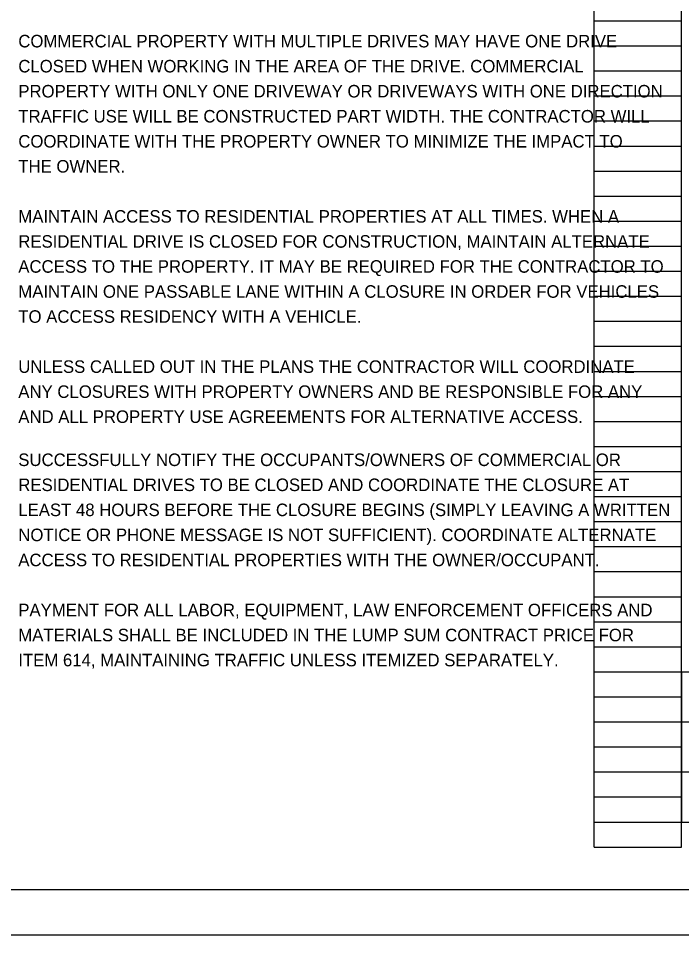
# Model space of a CAD drawing. Extents: x -1.3 to 43.7, y -2.4 to 22.
# Drawn here: x 17.24 to 24.66, y 0 to 10.25 of the extents above; entities that cross this region are included whole.
import ezdxf

# ---------------------------------------------------------------- set-up
doc = ezdxf.new("R2010")
doc.units = 0
for name, color, linetype in [('SH_Border', 7, 'Continuous'), ('SH_Cut_Line', 7, 'Continuous'), ('SH_Data', 7, 'Continuous'), ('SH_Text', 7, 'Continuous')]:
    doc.layers.add(name, color=color, linetype=linetype)

msp = doc.modelspace()

# ---------------------------------------------------------------- linework, layer by layer
at = {"layer": 'SH_Border'}
msp.add_lwpolyline([(1.5, 21.5), (33.5, 21.5), (33.5, 0.5), (1.5, 0.5)], close=True, dxfattribs=at)
at = {"layer": 'SH_Cut_Line'}
msp.add_lwpolyline([(0, 0), (34, 0), (34, 22), (0, 22)], close=True, dxfattribs=at)
at = {"layer": 'SH_Data'}
for p, q in [((23.68, 0.98), (23.68, 21.14)), ((24.66, 0.98), (24.66, 21.14)), ((23.68, 10.22), (24.66, 10.22)), ((23.68, 9.94), (24.66, 9.94)), ((23.68, 9.66), (24.66, 9.66)), ((23.68, 9.38), (24.66, 9.38)), ((23.68, 9.1), (24.66, 9.1)), ((23.68, 8.82), (24.66, 8.82)), ((23.68, 8.54), (24.66, 8.54)), ((23.68, 8.26), (24.66, 8.26)), ((23.68, 7.98), (24.66, 7.98)), ((23.68, 7.7), (24.66, 7.7)), ((23.68, 7.42), (24.66, 7.42)), ((23.68, 7.14), (24.66, 7.14)), ((23.68, 6.86), (24.66, 6.86)), ((23.68, 6.58), (24.66, 6.58)), ((23.68, 6.3), (24.66, 6.3)), ((23.68, 6.02), (24.66, 6.02)), ((23.68, 5.74), (24.66, 5.74)), ((23.68, 5.46), (24.66, 5.46)), ((23.68, 5.18), (24.66, 5.18)), ((23.68, 4.9), (24.66, 4.9)), ((23.68, 4.62), (24.66, 4.62)), ((23.68, 4.34), (24.66, 4.34)), ((23.68, 4.06), (24.66, 4.06)), ((23.68, 3.78), (24.66, 3.78)), ((23.68, 3.5), (24.66, 3.5)), ((23.68, 3.22), (24.66, 3.22)), ((23.68, 2.94), (24.66, 2.94)), ((23.68, 2.66), (24.66, 2.66)), ((23.68, 2.38), (24.66, 2.38)), ((23.68, 2.1), (24.66, 2.1)), ((23.68, 1.82), (24.66, 1.82)), ((23.68, 1.54), (24.66, 1.54)), ((23.68, 1.26), (24.66, 1.26)), ((23.68, 0.98), (24.66, 0.98))]:
    msp.add_line(p, q, dxfattribs=at)
at = {"layer": 'SH_Text'}
for p, q in [((24.66, 2.94), (31.1, 2.94)), ((24.66, 2.94), (24.66, 1.26)), ((24.66, 2.38), (31.1, 2.38)), ((24.66, 1.82), (31.1, 1.82)), ((24.66, 1.26), (31.1, 1.26))]:
    msp.add_line(p, q, dxfattribs=at)

# ---------------------------------------------------------------- texts
for s, p in [('COMMERCIAL PROPERTY WITH MULTIPLE DRIVES MAY HAVE ONE DRIVE ', (17.24, 9.923)), ('CLOSED WHEN WORKING IN THE AREA OF THE DRIVE. COMMERCIAL ', (17.24, 9.643)), ('PROPERTY WITH ONLY ONE DRIVEWAY OR DRIVEWAYS WITH ONE DIRECTION ', (17.24, 9.363)), ('TRAFFIC USE WILL BE CONSTRUCTED PART WIDTH. THE CONTRACTOR WILL ', (17.24, 9.083)), ('COORDINATE WITH THE PROPERTY OWNER TO MINIMIZE THE IMPACT TO ', (17.24, 8.803)), ('THE OWNER.', (17.24, 8.523)), ('MAINTAIN ACCESS TO RESIDENTIAL PROPERTIES AT ALL TIMES. WHEN A ', (17.24, 7.963)), ('RESIDENTIAL DRIVE IS CLOSED FOR CONSTRUCTION, MAINTAIN ALTERNATE ', (17.24, 7.683)), ('ACCESS TO THE PROPERTY. IT MAY BE REQUIRED FOR THE CONTRACTOR TO ', (17.24, 7.403)), ('MAINTAIN ONE PASSABLE LANE WITHIN A CLOSURE IN ORDER FOR VEHICLES ', (17.24, 7.123)), ('TO ACCESS RESIDENCY WITH A VEHICLE.', (17.24, 6.843)), ('UNLESS CALLED OUT IN THE PLANS THE CONTRACTOR WILL COORDINATE ', (17.24, 6.283)), ('ANY CLOSURES WITH PROPERTY OWNERS AND BE RESPONSIBLE FOR ANY ', (17.24, 6.003)), ('AND ALL PROPERTY USE AGREEMENTS FOR ALTERNATIVE ACCESS.', (17.24, 5.723)), ('SUCCESSFULLY NOTIFY THE OCCUPANTS/OWNERS OF COMMERCIAL OR ', (17.24, 5.241)), ('RESIDENTIAL DRIVES TO BE CLOSED AND COORDINATE THE CLOSURE AT ', (17.24, 4.961)), ('LEAST 48 HOURS BEFORE THE CLOSURE BEGINS (SIMPLY LEAVING A WRITTEN ', (17.24, 4.681)), ('NOTICE OR PHONE MESSAGE IS NOT SUFFICIENT). COORDINATE ALTERNATE ', (17.24, 4.401)), ('ACCESS TO RESIDENTIAL PROPERTIES WITH THE OWNER/OCCUPANT.', (17.24, 4.121)), ('PAYMENT FOR ALL LABOR, EQUIPMENT, LAW ENFORCEMENT OFFICERS AND ', (17.24, 3.561)), ('MATERIALS SHALL BE INCLUDED IN THE LUMP SUM CONTRACT PRICE FOR ', (17.24, 3.281)), ('ITEM 614, MAINTAINING TRAFFIC UNLESS ITEMIZED SEPARATELY.', (17.24, 3.001))]:
    msp.add_text(s, height=0.14, dxfattribs=at).set_placement(p)

doc.saveas('drawing.dxf')
